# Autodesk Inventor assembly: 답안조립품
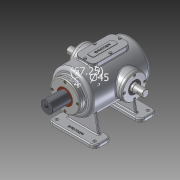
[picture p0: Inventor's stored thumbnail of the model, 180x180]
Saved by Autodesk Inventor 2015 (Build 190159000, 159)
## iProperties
Created: 2016-02
Part Number: 답안조립품
Document SubType Name: Assembly
Designer: Administrator
Author: Administrator
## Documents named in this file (15)
- C:\Users\Administrator\Desktop\360220V1004\답안조립품.iam
- C:\Users\Administrator\Desktop\360220V1004\본체.ipt
- C:\Users\Administrator\Desktop\360220V1004\상부커버.ipt
- C:\Users\Administrator\Desktop\360220V1004\육각머리볼트 M4.ipt
- C:\Users\Administrator\Desktop\360220V1004\슬라이드 커버.ipt
- C:\Users\Administrator\Desktop\360220V1004\볼트 M4x0.7.ipt
- C:\Users\Administrator\Desktop\360220V1004\베어링 6205.ipt
- 베어링 6205.ipt
- C:\Users\Administrator\Desktop\360220V1004\축 커버.ipt
- C:\Users\Administrator\Desktop\360220V1004\오일실.ipt
- 오일실.ipt
- C:\Users\Administrator\Desktop\360220V1004\편심축.ipt
- C:\Users\Administrator\Desktop\360220V1004\부시.ipt
- C:\Users\Administrator\Desktop\360220V1004\가변스프링.ipt
- C:\Users\Administrator\Desktop\360220V1004\슬라이드.ipt
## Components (13 placed, 2 different names)
1. 가변스프링:1
2. M4x0.7:1
3. M4x0.7:2
4. M4x0.7:3
5. M4x0.7:4
6. M4x0.7:5
7. M4x0.7:7
8. M4x0.7:8
9. M4x0.7:9
10. M4x0.7:6
11. M4x0.7:10
12. M4x0.7:11
13. M4x0.7:12
